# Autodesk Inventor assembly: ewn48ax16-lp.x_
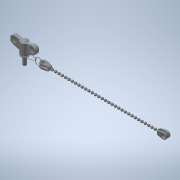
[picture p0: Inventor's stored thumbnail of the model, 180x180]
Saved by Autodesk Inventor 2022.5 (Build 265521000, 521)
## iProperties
Created: 2021-08
Part Number: ewn48ax16-lp.x_
Material: 一般
Document SubType Name: Assembly
Designer: ImaoCorp
Sending System: SOLIDWORKS 2019-2019304
MC: AMD64
MC_MODEL: Intel64 Family 6 Model 60 Stepping 3, GenuineIntel
OS: Windows_NT
FRU: Parasolid Version 31.0, build 290,  9- 1-2019
FORMAT: text
GUISE: transmit
KEY: ewn48ax16-lp
FILE: ewn48ax16-lp.x_t
DATE: Wed Aug 11 15:06:24 2021
Author: ImaoCorp
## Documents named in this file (3)
- X:\14_SW2022-Inv2022\00_全2023-1023新製品(TCC)まで\e\ewn48ax16-lp\EWN48AX16-LP.iam
- X:\14_SW2022-Inv2022\00_全2023-1023新製品(TCC)まで\e\ewn48ax16-lp\ewn48ax16-lp_01.ipt
- X:\14_SW2022-Inv2022\00_全2023-1023新製品(TCC)まで\e\ewn48ax16-lp\ewn48ax16-lp_02.ipt
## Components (2 placed, 2 different names)
1. ewn48ax16-lp_01
2. ewn48ax16-lp_02
